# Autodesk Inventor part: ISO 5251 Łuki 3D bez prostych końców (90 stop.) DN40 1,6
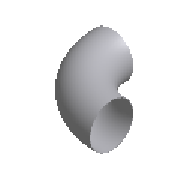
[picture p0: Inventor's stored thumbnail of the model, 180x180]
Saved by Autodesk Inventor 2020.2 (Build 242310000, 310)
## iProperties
Manager: www.cadconsulting.pl
Company: Fabian Stasiak CAD Consulting
NAME: PIPING: ISO 5251 Bend 3D
DATA: <meta><inlinegroups number="0" deflen="0"></inlinegroups><connections number="2"></connections><angles><a>1.57079632679489</a></angles></meta>
IsCustomPart: 0
Created: 2014-02
Part Number: ISO 5251 Łuki 3D bez prostych końców (90 stop.) DN40 1,6
Material: Stal nierdzewna
Description: Elementy ze stali nierdzewnej do przyspawania - Łuki 3D bez prostych końców (90 stop.)
Document SubType Name: Modeling
Standard: ISO 5251
Designer: F.Stasiak
Standard Revision: First edition 1981-04-15
Standards Organization: ISO
Language: pl-PL
Size Designation: DN40 1,6
Categories: <MemberInstance><Categories><Category DisplayName="Rury cienko- i grubościenne" InternalName="4347fa0f-2144-441d-94cd-e3e15c92b736" Mnemonic="TUBEANDPIPE"><Cate
Density: 1 g/cm^3
Appearance: Częściowo polerowana
Catalog Web Link: www.expertbooks.pl
Author: F.Stasiak
Subject: Zbiór ćwiczeń. Autodesk Inventor 2020. Kurs Professional
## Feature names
1. Sweep1
## Parameters: d0 = 45.1 mm, d1 = 48.3 mm, D = 48.3 mm, F1 = 57 mm, d2 = 57 mm, d3 = 57 mm, d4 = 0, T = 1.6 mm, d5 = 0, Size_Designation = 12.345 mm
